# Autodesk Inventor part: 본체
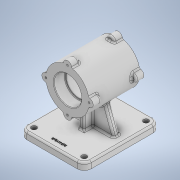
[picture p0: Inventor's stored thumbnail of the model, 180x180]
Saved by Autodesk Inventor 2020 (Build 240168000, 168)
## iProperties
Created: 2022-11
Part Number: 본체
Material: 일반
Document SubType Name: Modeling
Designer: owner
Density: 1 g/cm^3
Appearance: 기본값
Mass: 450.11 g
Surface Area: 796.622 cm^2
Volume: 450.11 cm^3
Author: owner
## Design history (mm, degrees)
sketch "스케치1"
  geometry: C1 r 37 at (0, 0); 1 further point
  constraints: 1 centre point, 1 coincident
  dimensions: "d0" = 74 diameter of C1
extrude "돌출1" new body sketch "스케치1" distance "d1" = 87; taper "d2" = 0 deg
sketch "스케치2"
  geometry: C1 r 23.5 at (0, 0); 1 further point
  constraints: 1 centre point, 1 coincident
  dimensions: "d3" = 47 diameter of C1
extrude "돌출2" cut sketch "스케치2" distance "d4" = 19; taper "d5" = 0 deg
sketch "스케치3"
  geometry: C1 r 7 at (0, 37); 2 further points
  constraints: 1 centre point, 1 vertical alignment, 1 other
  dimensions: "d6" = 14 diameter of C1
extrude "돌출3" join sketch "스케치3" distance "d7" = 14; taper "d8" = 0 deg
sketch "스케치4"
  geometry: C1 r 7 at (-37, 0); C2 r 7 at (0, -37); C3 r 7 at (37, 0); A1 r 37 centre (0, 0) between (-37, 0) and (0, -37) reference; 1 further point
  constraints: 3 centre point, 3 point on circle
  dimensions: "d9" = 14 diameter of C1; "d10" = 14 diameter of C2; "d11" = 14 diameter of C3
extrude "돌출4" join sketch "스케치4" distance "d12" = 14; taper "d13" = 0 deg
sketch "스케치5"
  geometry: C1 r 7 at (-37, 0); A1 r 37 centre (0, 0) between (-6.969, 36.338) and (-6.969, -36.338) reference; 1 further point
  constraints: 1 centre point, 1 point on circle
  dimensions: "d14" = 14 diameter of C1
extrude "돌출5" join sketch "스케치5" distance "d15" = 14; taper "d16" = 0 deg
sketch "스케치6"
  geometry: C1 r 23.5 at (0, 0); 1 further point
  constraints: 1 centre point, 1 coincident
  dimensions: "d17" = 47 diameter of C1
extrude "돌출6" cut sketch "스케치6" distance "d18" = 19; taper "d19" = 0 deg
sketch "스케치7"
  geometry: C1 r 7 at (0, 37); C2 r 7 at (-37, 0); C3 r 7 at (0, -37); C4 r 7 at (37, 0); A1 r 37 centre (0, 0) between (0, 37) and (-37, 0) reference; A2 r 7 centre (37, 0) between (36.338, -6.969) and (36.338, 6.969) reference; 3 further points
  constraints: 4 centre point, 3 point on circle, 1 coincident
  dimensions: "d20" = 14 diameter of C1; "d21" = 14 diameter of C2; "d22" = 14 diameter of C3; "d23" = 14 diameter of C4
extrude "돌출7" join sketch "스케치7" distance "d24" = 14; taper "d25" = 0 deg
sketch "스케치8"
  geometry: C1 r 21 at (0, 0); 1 further point
  constraints: 1 centre point, 1 coincident
  dimensions: "d26" = 42 diameter of C1
extrude "돌출8" cut sketch "스케치8" stored distance "d27" = 19; taper "d28" = 0 deg
sketch "스케치9"
  geometry: A1 r 7 centre (0, 37) between (6.969, 36.338) and (-6.969, 36.338) reference; 2 further points
  constraints: 1 coincident
hole "구멍1" sketch "스케치9" at (0, 37) diameter "d29" = 3.242; stored, may be unused: countersink angle "d33" = 90 deg, drill point angle "d35" = 118 deg; dims "d30" = 8, "d31" = 4, "d32" = 2, "d34" = 10
sketch "스케치10"
  geometry: C1 r 1.621 at (0, 37) reference; 2 further points
  constraints: 1 coincident
hole "구멍2" sketch "스케치10" at (0, 37) diameter "d39" = 3.242; stored, may be unused: countersink angle "d43" = 90 deg, drill point angle "d45" = 118 deg; dims "d40" = 8, "d41" = 4, "d42" = 2, "d44" = 10
node "작업 평면1"
node "작업 평면2"
sketch "스케치13"
  geometry: L1 (55, 26.5)-(-55, 26.5); L2 (-55, 26.5)-(-55, -103.5); L3 (-55, -103.5)-(55, -103.5); L4 (55, -103.5)-(55, 26.5); L5 (55, 26.5)-(-55, -103.5); L6 (-55, 26.5)-(55, -103.5); 4 further points
  constraints: 12 end point, 3 midpoint, 2 parallel, 1 horizontal, 1 perpendicular, 1 vertical alignment
  dimensions: "d67" = 110 distance of L3.end L2.end; "d68" = 130 distance of L2.end L1.end; "d69" = 43.5 vertical distance of point (25.568, -43.5) point (0, 0); "d70" = 70 distance from line of point (25.568, -43.5) L1
extrude "돌출10" join sketch "스케치13" distance "d71" = 12; taper "d72" = 0 deg
node "작업 평면3"
sketch "스케치17"
  geometry: L1 (-55, -26.5)-(55, -26.5) reference; L2 (-55, 103.5)-(-55, -26.5) reference; L3 (55, -26.5)-(55, 103.5) reference; L4 (55, 103.5)-(-55, 103.5) reference; 5 further points
  dimensions: "d99" = 12 distance from line of L1 point (-43, -14.5); "d100" = 12 distance from line of L2 point (-43, -14.5); "d101" = 12 distance from line of L3 point (43, -14.5); "d102" = 12 distance from line of L1 point (43, -14.5); "d104" = 12 distance from line of L4 point (43, 91.5); "d105" = 12 distance from line of L3 point (43, 91.5); "d106" = 12 distance from line of L4 point (-43, 91.5); "d107" = 12 distance from line of L2 point (-43, 91.5)
hole "구멍3" sketch "스케치17" at (43, -14.5), (43, 91.5), (-43, 91.5), (-43, -14.5) diameter "d108" = 9; stored, may be unused: countersink angle "d112" = 90 deg, drill point angle "d114" = 118 deg; dims "d109" = 24, "d110" = 4, "d111" = 2, "d113" = 32.3
node "작업 평면4"
sketch "스케치18"
  geometry: L1 (55, -70)-(-55, -70) reference; L2 (-25.336, -26.964)-(-41, -70); L3 (25.336, -26.964)-(41, -70); A1 r 37 centre (0, 0) between (-36.338, -6.969) and (-6.969, -36.338) reference; A2 r 37 centre (0, 0) between (6.969, -36.338) and (36.338, -6.969) reference; A3 r 37 centre (0, 0) between (-6.969, -36.338) and (6.969, -36.338) reference; 1 further point
  constraints: 4 end point, 2 point on circle, 2 point on line
  dimensions: "d116" = 110 deg angle of L1 L2; "d117" = 14 distance of L1.end L2.end; "d118" = 14 distance of L1.start L3.end; "d119" = 110 deg angle of L1 L3
extrude "돌출12" join sketch "스케치18" stored distance "d120" = 10; taper "d121" = 0 deg
sketch "스케치19"
  geometry: L1 (-37, -14)-(-37, -73) reference; L2 (-37, -23.5)-(-70, -23.5); L3 (-70, -103.5)-(-70, 26.5) reference; L4 (-37, -63.5)-(-70, -63.5); L5 (-70, -38.5)-(-26.964, -38.5) reference; L6 (-26.964, -48.5)-(-70, -48.5) reference; 1 further point
  constraints: 4 end point, 2 horizontal, 2 point on line
  dimensions: "d122" = 15 distance between parallel lines of L5 L2; "d123" = 15 distance between parallel lines of L6 L4
feature "리브3" sketch "스케치19" dims "d124" = 1, "d125" = 10, "d126" = 0, "d127" = 0, "d128" = 1, "d129" = 1
sketch "스케치20"
  geometry: L1 (-37, -14)-(-37, -73) reference; L2 (-37, -63.5)-(-70, -63.5); L3 (-70, 26.5)-(-70, -103.5) reference; L4 (-26.964, -48.5)-(-70, -48.5) reference; 1 further point
  constraints: 2 end point, 2 point on line, 1 horizontal
  dimensions: "d130" = 15 distance between parallel lines of L4 L2
feature "리브4" sketch "스케치20" dims "d131" = 1, "d132" = 10, "d133" = 0, "d134" = 0, "d135" = 1, "d136" = 1
fillet "모깎기4" dims "d137" = 3
fillet "모깎기5" dims "d138" = 12
fillet "모깎기6" dims "d139" = 3
fillet "모깎기7" dims "d140" = 3
fillet "모깎기8" dims "d141" = 3
sketch "스케치21"
  geometry: L1 (-6.889, 0)-(6.889, 0) reference; L2 (-43, -26.5)-(43, -26.5) reference; 3 further points
  constraints: 1 midpoint, 1 vertical alignment, 1 other
  dimensions: "d142" = 12 distance from line of L2 point (0, -14.5)
feature "엠보싱1" sketch "스케치21" dims "d11" = 14, "d143" = 0.5, "d144" = 0
fillet "모깎기9" dims "d145" = 1
chamfer "모따기1" distance "d146" = 1; stored, may be unused: second distance "d147" = 2, angle "d148" = 45 deg
node "솔리드1"
pattern_circular "원형 패턴1" dims angle "d37" = 360 deg
pattern_circular "원형 패턴2" dims angle "d47" = 360 deg
feature "A9D066F2-1C7D-4E18-AEED-F7BC21143FA4" dims "d108" = 9, "d109" = 24, "d110" = 4, "d111" = 2, "d112" = 90 deg, "d113" = 32.3, "d114" = 118 deg
other parameters: "d49" = -82, "d54" = -43.5, "d73" = -43.5, "d115" = -43.5
